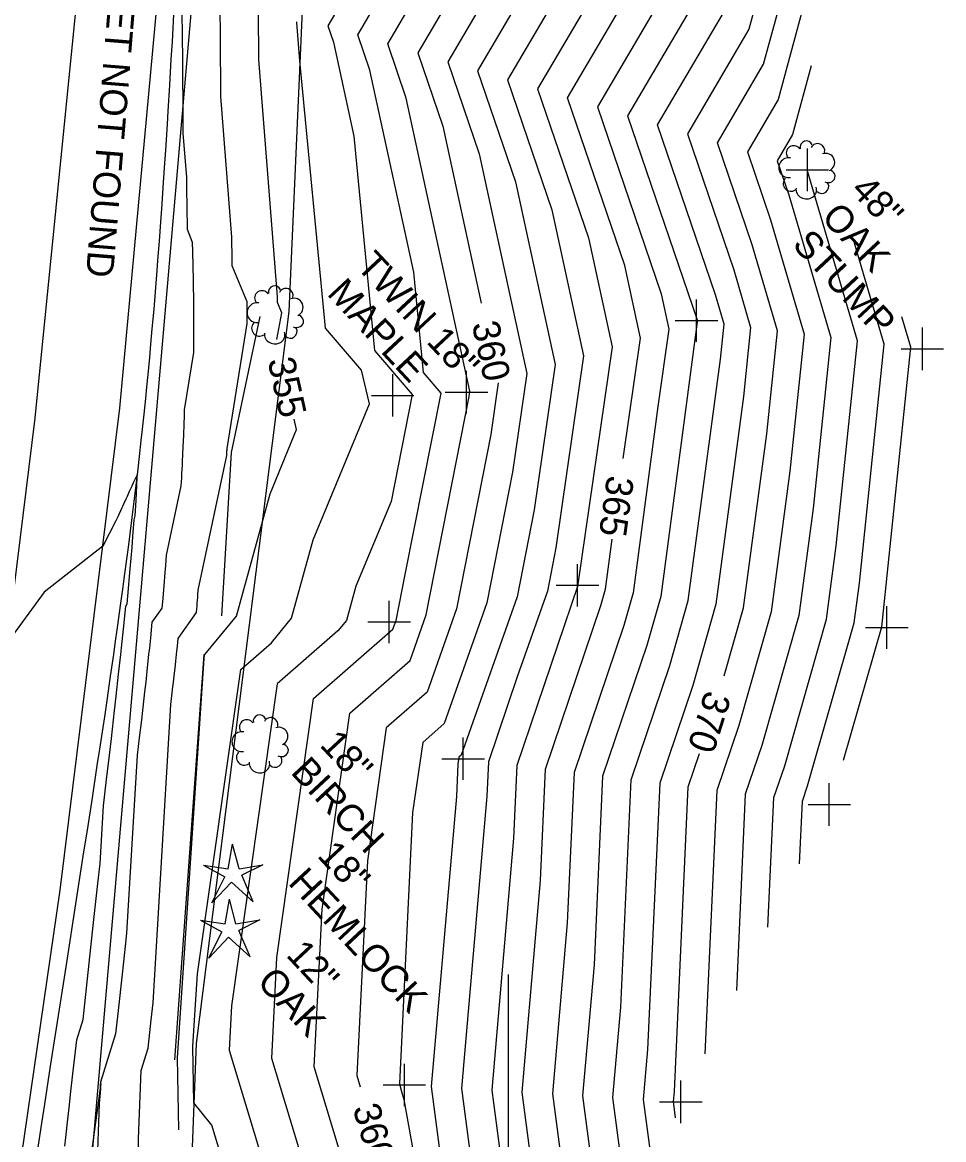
# Model space of a CAD drawing. Extents: x 487096 to 489566, y 221939 to 224454.
# Drawn here: x 488442.7 to 488551.3, y 223219.9 to 223351.6 of the extents above; entities that cross this region are included whole.
import ezdxf

# ---------------------------------------------------------------- set-up
doc = ezdxf.new("R2010")
doc.units = 0
for name, color, linetype in [('SV_BKLN_EARTH_TOP', 7, 'Continuous'), ('SV_DRAN_DRAN_TX', 7, 'Continuous'), ('SV_GRID_GRID', 7, 'Continuous'), ('SV_ROAD_BITRD', 7, 'Continuous'), ('SV_ROWL_HWYLOC', 7, 'Continuous'), ('SV_SURF_INDEX_CONTOUR', 7, 'Continuous'), ('SV_SURF_INTER_CONTOUR', 7, 'Continuous'), ('SV_SURF_SPOT', 7, 'Continuous'), ('SV_TRAF_PVMTL', 7, 'Continuous'), ('SV_TREE_TREEVEG', 7, 'Continuous'), ('SV_TREE_TREEVEG_TX', 7, 'Continuous'), ('SV_UTOH_OVERHEAD_LINES', 7, 'Continuous'), ('SV_WALL_STONE_WALL', 7, 'Continuous')]:
    doc.layers.add(name, color=color, linetype=linetype)

msp = doc.modelspace()

# ---------------------------------------------------------------- linework, layer by layer
at = {"layer": 'SV_BKLN_EARTH_TOP'}
for points in [[(488466.19, 223281.65), (488467.35, 223300.89), (488470.72, 223316.91)], [(488425.92, 222945.04), (488428.16, 222977.23), (488428.57, 223001.38), (488431.19, 223029.45), (488433.27, 223064.76), (488435.62, 223093.09), (488438.49, 223133.72), (488441.68, 223167.83), (488447.06, 223190.64), (488452, 223226.55)]]:
    msp.add_lwpolyline(points, dxfattribs=at)
at = {"layer": 'SV_GRID_GRID'}
msp.add_line((488500, 223200), (488500, 223239.37), dxfattribs=at)
at = {"layer": 'SV_ROAD_BITRD'}
msp.add_lwpolyline([(488444.48, 223218.5), (488444.99, 223221.86), (488445.33, 223224.1), (488446.03, 223228.58), (488447.07, 223235.3), (488447.77, 223239.78), (488449.17, 223248.74), (488449.96, 223253.83), (488450.36, 223256.38), (488450.95, 223260.2), (488451.53, 223264.02), (488451.82, 223265.93), (488452.21, 223268.48), (488452.4, 223269.75), (488452.68, 223271.66), (488453.1, 223274.53), (488453.47, 223277.08), (488453.65, 223278.36), (488453.92, 223280.27), (488454.32, 223283.14), (488454.58, 223285.05), (488454.71, 223286.01), (488454.9, 223287.45), (488455.23, 223290), (488455.4, 223291.28), (488455.64, 223293.2), (488455.87, 223295.11), (488455.99, 223296.07), (488456.22, 223297.99), (488456.33, 223298.95), (488456.49, 223300.39), (488456.71, 223302.3), (488456.81, 223303.26), (488456.97, 223304.7), (488457.19, 223306.86), (488457.37, 223308.58), (488457.48, 223309.73), (488457.7, 223312.02), (488457.81, 223313.16), (488458.01, 223315.45), (488458.21, 223317.75), (488458.34, 223319.28), (488458.42, 223320.3), (488458.59, 223322.33), (488458.67, 223323.48), (488458.85, 223325.78), (488459.02, 223328.07), (488459.13, 223329.6), (488459.34, 223332.67), (488459.49, 223334.96), (488459.59, 223336.49), (488459.79, 223339.56), (488459.88, 223341.09), (488460.07, 223344.16), (488460.25, 223347.22), (488460.37, 223349.27), (488460.6, 223353.35)], dxfattribs=at)
at = {"layer": 'SV_ROWL_HWYLOC'}
msp.add_lwpolyline([(487756.92, 223854.03), (487819.74, 223823.93), (487982.51, 223759.36), (488009.69, 223754.74), (488041.14, 223750.63), (488071.96, 223735.45), (488100.92, 223722.74), (488124.66, 223715.6), (488155.68, 223709.25), (488178.9, 223706.07), (488296.16, 223658.56), (488379.4, 223617.17), (488410.15, 223595.68), (488443.8, 223549.21), (488472.24, 223469.86), (488477.06, 223418.16), (488475.62, 223352.08), (488474.08, 223317.48), (488463.17, 223231.25), (488461.58, 223189.46)], dxfattribs=at)
at = {"layer": 'SV_SURF_INDEX_CONTOUR'}
for points in [[(488472.68, 223314.2), (488473.26, 223317.34), (488472.77, 223318.55), (488472.76, 223318.84), (488472.76, 223319.06), (488472.76, 223319.22), (488470.57, 223347.17), (488470.56, 223348.08), (488470.56, 223348.55), (488470.55, 223349.5), (488470.54, 223350.48), (488470.54, 223351.14), (488470.53, 223352.51), (488470.52, 223353.97), (488470.51, 223354.72), (488470.5, 223355.87), (488470.49, 223357.06), (488470.48, 223357.66), (488470.47, 223358.89), (488470.46, 223359.52), (488470.45, 223360.48), (488470.43, 223361.35), (488472.26, 223368.45), (488472.11, 223400.06)], [(488511.73, 223397.36), (488512.13, 223394.53), (488512.98, 223388.83), (488512.99, 223388.54), (488512.85, 223388.04), (488489.29, 223347.98), (488492.23, 223339.34), (488496.76, 223318.46)], [(488513.5, 223300.19), (488515.54, 223314.36), (488513.69, 223322.89), (488506.94, 223342.67), (488521.45, 223367.33), (488525.06, 223380.67)], [(488525.4, 223274.55), (488527.68, 223282.57), (488530.41, 223303.07), (488531.67, 223315.22), (488528.7, 223325.34), (488524.6, 223337.37), (488530.04, 223346.62), (488532.96, 223357.41)], [(488539.47, 223264.61), (488543.97, 223280.34), (488544.06, 223281.07), (488547.39, 223313.27), (488546.33, 223316.87)], [(488498.77, 223309.07), (488497.9, 223303.01), (488493.87, 223282.47), (488490.39, 223272.65), (488485.58, 223268.44), (488483.35, 223252.76), (488482.11, 223227.48), (488482.51, 223226.16)], [(488461.14, 223221.08), (488460.98, 223229.57), (488464.11, 223276.6), (488464.17, 223277.05), (488464.21, 223277.09), (488467.94, 223281.58), (488471.88, 223296.01), (488475.02, 223303.6), (488474.74, 223304.82)], [(488504.19, 223205.76), (488501.58, 223225.52), (488503.75, 223250.45), (488504.35, 223263.58), (488510.85, 223282.86), (488511.4, 223284.79), (488512.19, 223290.68)], [(488519.68, 223222.48), (488519.43, 223224.43), (488519.53, 223225.58), (488521.17, 223261.48), (488522.49, 223265.41)]]:
    msp.add_lwpolyline(points, dxfattribs=at)
at = {"layer": 'SV_SURF_INTER_CONTOUR'}
for points in [[(488500.88, 223491.69), (488499, 223452.51), (488502.73, 223430.62), (488512.04, 223423.69), (488513.53, 223417.73), (488517.77, 223389.17), (488517.92, 223385.76), (488516.29, 223379.76), (488496.35, 223345.85), (488500.81, 223332.76), (488505.49, 223311.23), (488503.02, 223294.11), (488501.01, 223283.86), (488494.41, 223265.22), (488494.15, 223265), (488494.03, 223264.14), (488493.84, 223260.36), (488490.87, 223226.17), (488492.01, 223217.49)], [(488503.21, 223489.06), (488501.45, 223452.25), (488504.95, 223431.69), (488513.7, 223425.18), (488516.53, 223413.9), (488520.17, 223389.34), (488520.38, 223384.37), (488518.01, 223375.61), (488499.88, 223344.79), (488505.11, 223329.47), (488508.84, 223312.28), (488505.58, 223289.65), (488504.58, 223284.55), (488501, 223274.45), (488497.62, 223264.42), (488497.44, 223260.4), (488494.44, 223225.95), (488496.88, 223207.44)], [(488505.54, 223486.42), (488503.89, 223452), (488507.17, 223432.76), (488515.35, 223426.67), (488519.52, 223410.07), (488522.57, 223389.51), (488522.84, 223382.98), (488519.73, 223371.47), (488503.41, 223343.73), (488509.4, 223326.18), (488512.19, 223313.32), (488508.16, 223285.35), (488508.15, 223285.24), (488508.14, 223285.22), (488500.98, 223264), (488500.59, 223255.42), (488498.01, 223225.74), (488501.75, 223197.38)], [(488510.21, 223481.15), (488508.79, 223451.48), (488511.61, 223434.9), (488518.66, 223429.65), (488525.5, 223402.41), (488527.36, 223389.85), (488527.77, 223380.2), (488523.16, 223363.19), (488510.47, 223341.61), (488517.98, 223319.59), (488518.89, 223315.4), (488517.58, 223306.28), (488514.66, 223284.35), (488513.56, 223280.5), (488507.71, 223263.16), (488506.9, 223245.48), (488505.15, 223225.3), (488509.67, 223191.06)], [(488512.54, 223478.52), (488511.24, 223451.22), (488513.83, 223435.97), (488520.32, 223431.14), (488528.49, 223398.58), (488529.76, 223390.02), (488530.23, 223378.81), (488524.88, 223359.04), (488514, 223340.55), (488522.2, 223316.5), (488522.24, 223316.4), (488522.22, 223316.27), (488517.92, 223283.9), (488516.27, 223278.14), (488511.07, 223262.74), (488510.06, 223240.5), (488508.72, 223225.09), (488512.17, 223198.92)], [(488514.68, 223206.77), (488512.29, 223224.87), (488513.21, 223235.53), (488514.44, 223262.32), (488518.98, 223275.78), (488521.17, 223283.46), (488524.95, 223311.87), (488525.38, 223316), (488524.37, 223319.45), (488517.53, 223339.49), (488526.6, 223354.9), (488532.69, 223377.42), (488532.16, 223390.19), (488531.48, 223394.75), (488521.97, 223432.64), (488516.05, 223437.04), (488513.68, 223450.96), (488514.87, 223475.88)], [(488517.21, 223473.25), (488516.13, 223450.71), (488518.27, 223438.11), (488523.63, 223434.13), (488534.47, 223390.92), (488534.56, 223390.36), (488535.16, 223376.03), (488528.32, 223350.76), (488521.06, 223338.43), (488526.53, 223322.39), (488528.52, 223315.61), (488527.68, 223307.47), (488524.43, 223283.01), (488521.69, 223273.42), (488517.8, 223261.9), (488516.37, 223230.56), (488515.86, 223224.65), (488517.18, 223214.63)], [(488514.57, 223383.9), (488492.82, 223346.91), (488496.52, 223336.05), (488502.14, 223310.19), (488500.46, 223298.56), (488497.44, 223283.16), (488492.4, 223268.94), (488489.87, 223266.72), (488488.69, 223258.45), (488487.13, 223226.48), (488487.39, 223225.61), (488487.66, 223224.66), (488494.52, 223186.34)], [(488481.85, 223212.78), (488477.1, 223228.48), (488478.01, 223247.07), (488481.3, 223270.16), (488488.38, 223276.36), (488490.3, 223281.77), (488495.34, 223307.46), (488495.43, 223308.11), (488487.94, 223342.63), (488485.76, 223349.04), (488504.36, 223380.67)], [(488479.08, 223206.36), (488472.09, 223229.47), (488472.67, 223241.38), (488477.02, 223271.88), (488486.37, 223280.07), (488486.73, 223281.08), (488487.79, 223286.49), (488492.04, 223307.86), (488489.95, 223310.29), (488488.82, 223322.12), (488483.65, 223345.93), (488482.23, 223350.1), (488494.35, 223370.71)], [(488484.34, 223360.75), (488478.7, 223351.16), (488479.36, 223349.22), (488481.76, 223338.14), (488484.19, 223312.9), (488488.65, 223307.71), (488486.14, 223295.11), (488482.01, 223285.12), (488480.91, 223281.1), (488479.88, 223279.85), (488472.74, 223273.61), (488467.33, 223235.69), (488467.07, 223230.47), (488476.31, 223199.95)], [(488536.13, 223358.63), (488531.76, 223342.48), (488528.13, 223336.31), (488530.86, 223328.28), (488534.81, 223314.83), (488533.14, 223298.67), (488530.94, 223282.12), (488527.11, 223268.7), (488524.53, 223261.06), (488523.11, 223230.04)], [(488461.5, 223353.28), (488461.54, 223349.48), (488461.55, 223347.63), (488461.57, 223344.92), (488461.59, 223342.29), (488461.6, 223340.99), (488461.61, 223338.46), (488462.02, 223333.31), (488462.04, 223331.91), (488462.07, 223329.86), (488462.1, 223327.2), (488462.72, 223325.67), (488462.75, 223324.52), (488462.78, 223322.84), (488462.81, 223321.22), (488462.83, 223320.44), (488462.85, 223319.08), (488462.85, 223318.41), (488462.86, 223317.44), (488462.87, 223316.01), (488462.87, 223314.63), (488462.87, 223313.96), (488462.86, 223312.65), (488461.77, 223305.89), (488461.75, 223305.2), (488461.72, 223304.2), (488461.68, 223302.97), (488461.65, 223302.17), (488461.62, 223301.65), (488461.58, 223300.62), (488461.54, 223299.86), (488461.52, 223299.37), (488461.46, 223298.39), (488461.44, 223297.91), (488461.38, 223296.97), (488459.65, 223288.8), (488459.56, 223287.56), (488459.5, 223286.75), (488459.37, 223285.15), (488459.29, 223284.27), (488459.24, 223283.69), (488459.14, 223282.53), (488457.97, 223280.88), (488457.79, 223279.06), (488457.66, 223277.86), (488457.58, 223277.08), (488457.41, 223275.53), (488457.23, 223273.81), (488457.1, 223272.69), (488457.02, 223271.95), (488456.85, 223270.48), (488456.72, 223269.4), (488456.48, 223267.28), (488456.23, 223265.21), (488454.98, 223244.24), (488454.81, 223242.72), (488454.48, 223239.76), (488453.94, 223234.77), (488453.69, 223232.39), (488451.91, 223226.71), (488451.9, 223226.58), (488451.89, 223226.5), (488451.89, 223226.47), (488451.88, 223226.41), (488451.87, 223226.34), (488451.87, 223226.31), (488451.86, 223226.26), (488451.92, 223225.91), (488451.76, 223224.18), (488451.2, 223208.62)], [(488456.68, 223196.26), (488456.4, 223220), (488456.69, 223228.05), (488457.52, 223230.71), (488457.63, 223231.78), (488457.88, 223234.02), (488458.02, 223235.36), (488458.1, 223236.04), (488460.2, 223271.18), (488460.32, 223272.21), (488460.44, 223273.26), (488460.51, 223273.8), (488460.59, 223274.53), (488460.63, 223274.89), (488460.69, 223275.45), (488460.79, 223276.3), (488460.87, 223277.07), (488460.91, 223277.46), (488460.97, 223278.06), (488461.06, 223278.96), (488463.22, 223282.02), (488463.26, 223282.51), (488463.28, 223282.75), (488463.31, 223283.13), (488463.37, 223283.8), (488463.39, 223284.14), (488463.43, 223284.66), (488466.78, 223300.51), (488466.79, 223300.6), (488466.79, 223300.65), (488466.8, 223300.74), (488466.8, 223300.79), (488466.8, 223300.86), (488466.81, 223300.96), (488466.81, 223301.01), (488466.81, 223301.09), (488466.82, 223301.2), (488466.82, 223301.3), (488466.82, 223301.36), (488469.2, 223316.09), (488469.2, 223316.34), (488469.2, 223316.47), (488469.2, 223316.74), (488469.2, 223317.01), (488469.2, 223317.2), (488469.2, 223317.33), (488469.19, 223317.59), (488469.19, 223317.75), (488469.19, 223318.06), (488469.18, 223318.38), (488469.17, 223318.61), (488467.43, 223322.87), (488467.41, 223324.35), (488467.4, 223325.49), (488467.39, 223326.26), (488466.09, 223342.81), (488466.08, 223344.54), (488466.08, 223345.42), (488466.06, 223347.21), (488466.05, 223349.06), (488466.04, 223350.31), (488466.02, 223352.9)], [(488473.54, 223193.53), (488465.04, 223221.63), (488462.9, 223224.26), (488462.77, 223230.95), (488463.34, 223239.44), (488468.45, 223275.33), (488472.04, 223278.47), (488474.43, 223281.34), (488476.95, 223290.57), (488483.59, 223306.63), (488482.68, 223310.56), (488478.43, 223315.51), (488475.4, 223347.01), (488475.04, 223351.52), (488475.04, 223351.62)], [(488535.66, 223346.42), (488533.47, 223338.33), (488531.66, 223335.25), (488533.03, 223331.23), (488537.96, 223314.44), (488535.87, 223294.27), (488534.2, 223281.68), (488529.82, 223266.34), (488527.89, 223260.64), (488526.84, 223237.49)], [(488530.56, 223244.95), (488531.26, 223260.22), (488532.53, 223263.98), (488537.45, 223281.23), (488538.6, 223289.87), (488541.1, 223314.05), (488535.19, 223334.17), (488535.19, 223334.18), (488535.19, 223334.19), (488535.2, 223334.21)], [(488534.28, 223252.41), (488534.62, 223259.8), (488535.23, 223261.62), (488540.71, 223280.79), (488541.33, 223285.47), (488544.25, 223313.66), (488540.76, 223325.54)], [(488447.72, 223219.15), (488447.83, 223220.18), (488448.07, 223222.34), (488448.25, 223224.04), (488448.38, 223225.22), (488448.66, 223227.68), (488449.11, 223231.68), (488449.86, 223234.07), (488450.25, 223237.77), (488451.09, 223245.49), (488451.6, 223250.08), (488451.86, 223252.44), (488452.26, 223259.25), (488452.63, 223262.36), (488453, 223265.55), (488453.19, 223267.17), (488453.44, 223269.37), (488453.57, 223270.48), (488453.76, 223272.17), (488454.04, 223274.75), (488454.29, 223277.08), (488454.42, 223278.26), (488454.6, 223280.06), (488454.88, 223282.79), (488455.06, 223283.05), (488455.22, 223284.87), (488455.3, 223285.79), (488455.42, 223287.18), (488455.63, 223289.7), (488455.73, 223290.98), (488455.88, 223292.93), (488455.98, 223293.42), (488456.09, 223295.22), (488456.14, 223296.13), (488456.24, 223297.99), (488456.25, 223298.31), (488456.18, 223298.15), (488455.77, 223297.29), (488455.59, 223296.92), (488455.29, 223296.27), (488455.03, 223295.71), (488454.88, 223295.39), (488454.61, 223294.81), (488454.48, 223294.52), (488454.4, 223294.34), (488454.25, 223294.01), (488454.05, 223293.56), (488453.93, 223293.3), (488453.86, 223293.13), (488453.72, 223292.83), (488452.16, 223289.83), (488445.28, 223284.43), (488440.92, 223278.47)]]:
    msp.add_lwpolyline(points, dxfattribs=at)
at = {"layer": 'SV_SURF_SPOT'}
for p, q in [((488535.2, 223331.68), (488535.2, 223336.68)), ((488532.7, 223334.18), (488537.7, 223334.18)), ((488535.2, 223334.18), (488535.2, 223334.18)), ((488522.14, 223313.91), (488522.14, 223318.91)), ((488519.63, 223316.41), (488524.64, 223316.41)), ((488522.14, 223316.41), (488522.14, 223316.41)), ((488548.76, 223310.59), (488548.76, 223315.6)), ((488546.26, 223313.1), (488551.26, 223313.1)), ((488548.76, 223313.1), (488548.76, 223313.1)), ((488495.04, 223305.49), (488495.04, 223310.49)), ((488486.34, 223305.11), (488486.34, 223310.11)), ((488492.54, 223307.99), (488497.54, 223307.99)), ((488495.04, 223307.99), (488495.04, 223307.99)), ((488483.84, 223307.61), (488488.84, 223307.61)), ((488486.34, 223307.61), (488486.34, 223307.61)), ((488508.12, 223282.74), (488508.12, 223287.74)), ((488505.61, 223285.24), (488510.62, 223285.24)), ((488508.12, 223285.24), (488508.12, 223285.24)), ((488485.91, 223278.42), (488485.91, 223283.42)), ((488544.57, 223277.76), (488544.57, 223282.76)), ((488483.41, 223280.92), (488488.42, 223280.92)), ((488485.91, 223280.92), (488485.91, 223280.92)), ((488542.07, 223280.26), (488547.07, 223280.26)), ((488544.57, 223280.26), (488544.57, 223280.26)), ((488494.64, 223262.3), (488494.64, 223267.3)), ((488492.14, 223264.8), (488497.14, 223264.8)), ((488494.64, 223264.8), (488494.64, 223264.8)), ((488537.78, 223256.9), (488537.78, 223261.9)), ((488535.28, 223259.4), (488540.28, 223259.4)), ((488537.78, 223259.4), (488537.78, 223259.4)), ((488487.72, 223223.86), (488487.72, 223228.86)), ((488485.22, 223226.36), (488490.22, 223226.36)), ((488487.72, 223226.36), (488487.72, 223226.36)), ((488520.29, 223221.88), (488520.29, 223226.88)), ((488517.79, 223224.38), (488522.79, 223224.38)), ((488520.29, 223224.38), (488520.29, 223224.38))]:
    msp.add_line(p, q, dxfattribs=at)
at = {"layer": 'SV_TRAF_PVMTL'}
for points in [[(488428.31, 223181.75), (488437.42, 223250.14), (488444.19, 223304.94), (488449.14, 223354.51)], [(488437.22, 223181.07), (488447.15, 223249.31), (488454.17, 223306.09), (488458.57, 223353.78)]]:
    msp.add_lwpolyline(points, dxfattribs=at)
at = {"layer": 'SV_TREE_TREEVEG'}
for p, q in [((488535.2, 223334.18), (488535.2, 223334.18)), ((488472.55, 223317.11), (488472.55, 223317.11)), ((488470.77, 223266.56), (488470.77, 223266.56)), ((488466.94, 223251.82), (488467.46, 223254.73)), ((488468.23, 223251.83), (488467.46, 223254.73)), ((488464.06, 223252.26), (488466.57, 223250.89)), ((488464.06, 223252.26), (488466.94, 223251.82)), ((488467.46, 223251.16), (488467.46, 223251.16)), ((488468.23, 223251.83), (488471.02, 223252.31)), ((488471.02, 223252.31), (488468.57, 223251.08)), ((488469.9, 223247.94), (488468.57, 223251.08)), ((488465.03, 223247.81), (488466.57, 223250.89)), ((488467.34, 223250.26), (488465.03, 223247.81)), ((488467.34, 223250.26), (488469.9, 223247.94)), ((488466.58, 223245.33), (488467.1, 223248.24)), ((488467.87, 223245.34), (488467.1, 223248.24)), ((488467.87, 223245.34), (488470.67, 223245.82)), ((488470.67, 223245.82), (488468.21, 223244.58)), ((488463.7, 223245.77), (488466.22, 223244.4)), ((488463.7, 223245.77), (488466.58, 223245.33)), ((488467.1, 223244.67), (488467.1, 223244.67)), ((488469.54, 223241.45), (488468.21, 223244.58)), ((488464.67, 223241.32), (488466.22, 223244.4)), ((488466.98, 223243.77), (488464.67, 223241.32)), ((488466.98, 223243.77), (488469.54, 223241.45))]:
    msp.add_line(p, q, dxfattribs=at)
for centre, radius, start, end in [((488533.59, 223336.15), 0.874, 35.9933, 211.459), ((488535.09, 223336.83), 0.75, 23.2911, 192.3579), ((488536.4, 223336.42), 0.85, 345.5308, 152.7093), ((488533, 223334.43), 1.17, 79.3292, 279.9889), ((488537.36, 223335.06), 1.06, 294.1859, 111.1082), ((488533.28, 223332.58), 0.922, 137.0157, 304.5501), ((488470.94, 223319.07), 0.874, 35.9933, 211.459), ((488472.44, 223319.76), 0.75, 23.2911, 192.3579), ((488473.76, 223319.35), 0.85, 345.5308, 152.7093), ((488470.35, 223317.35), 1.17, 79.3292, 279.9889), ((488474.72, 223317.99), 1.06, 294.1859, 111.1082), ((488470.64, 223315.51), 0.922, 137.0157, 304.5501), ((488470.65, 223269.21), 0.75, 23.2911, 192.3579), ((488471.97, 223268.8), 0.85, 345.5308, 152.7093), ((488469.15, 223268.52), 0.874, 35.9933, 211.459), ((488472.93, 223267.44), 1.06, 294.1859, 111.1082), ((488468.56, 223266.81), 1.17, 79.3292, 279.9889), ((488468.85, 223264.96), 0.922, 137.0157, 304.5501)]:
    msp.add_arc(centre, radius, start, end, dxfattribs=at)
for centre, major_axis, ratio, start_param, end_param in [((488537.65, 223333.41), (0.822, -0.013), 0.901056, 4.216583, 7.444153), ((488535.07, 223331.85), (-1.2, 0.16), 0.902156, 0, 3.5401), ((488536.92, 223332.21), (0.08, -0.798), 0.999752, 5.391582, 8.241319), ((488475.01, 223316.34), (0.822, -0.013), 0.901056, 4.216583, 7.444153), ((488472.43, 223314.77), (-1.2, 0.16), 0.902156, 0, 3.5401), ((488474.27, 223315.14), (0.08, -0.798), 0.999752, 5.391582, 8.241319), ((488473.22, 223265.79), (0.822, -0.013), 0.901056, 4.216583, 7.444153), ((488470.64, 223264.22), (-1.2, 0.16), 0.902156, 0, 3.5401), ((488472.48, 223264.59), (0.08, -0.798), 0.999752, 5.391582, 8.241319)]:
    msp.add_ellipse(centre, major_axis=major_axis, ratio=ratio, start_param=start_param, end_param=end_param, dxfattribs=at)
at = {"layer": 'SV_UTOH_OVERHEAD_LINES'}
msp.add_lwpolyline([(488477.01, 222631.44), (488424.13, 222778.25), (488391.68, 223012.96), (488449.87, 223205.72), (488470, 223438.33), (488349.56, 223622.89), (488159.18, 223693.12), (487993.17, 223755.78), (487804.2, 223830.22), (487742.26, 223860.21)], dxfattribs=at)
at = {"layer": 'SV_WALL_STONE_WALL'}
for points in [[(488485.21, 223429.22), (488484.6, 223419.11), (488477.06, 223418.16), (488475.62, 223352.08), (488474.08, 223317.48)], [(488460.65, 223229.33), (488464.12, 223277.07)], [(488463.17, 223231.25), (488461.58, 223189.46), (488458.34, 223164.64), (488456.44, 223151.49), (488462.52, 223138.88)]]:
    msp.add_lwpolyline(points, dxfattribs=at)

# ---------------------------------------------------------------- texts
at = {"layer": 'SV_DRAN_DRAN_TX'}
msp.add_text('INLET NOT FOUND', height=3.2, rotation=265.3488, dxfattribs=at).set_placement((488453.32, 223360.25))
at = {"layer": 'SV_SURF_INDEX_CONTOUR'}
for s, rotation, p in [('360', 282.0748, (488495.65, 223316.02)), ('355', 282.3635, (488471.58, 223311.75)), ('365', 262.1388, (488511.62, 223298.28)), ('370', 252.378, (488523.22, 223272.99)), ('360', 286.6183, (488481.59, 223223.64))]:
    msp.add_text(s, height=3.2, rotation=rotation, dxfattribs=at).set_placement(p)
at = {"layer": 'SV_TREE_TREEVEG_TX'}
for s, p in [('48"', (488540.17, 223331.68)), ('OAK', (488536.73, 223328.47)), ('STUMP', (488533.3, 223325.27)), ('TWIN 18"', (488481.93, 223322.73)), ('MAPLE', (488478.49, 223319.52)), ('18"', (488477.63, 223266.34)), ('BIRCH', (488474.2, 223263.14)), ('18"', (488477.33, 223253.3)), ('HEMLOCK', (488473.9, 223250.09)), ('12"', (488473.66, 223241.6)), ('OAK', (488470.22, 223238.39))]:
    msp.add_text(s, height=3.2, rotation=313.0386, dxfattribs=at).set_placement(p)

doc.saveas('drawing.dxf')
